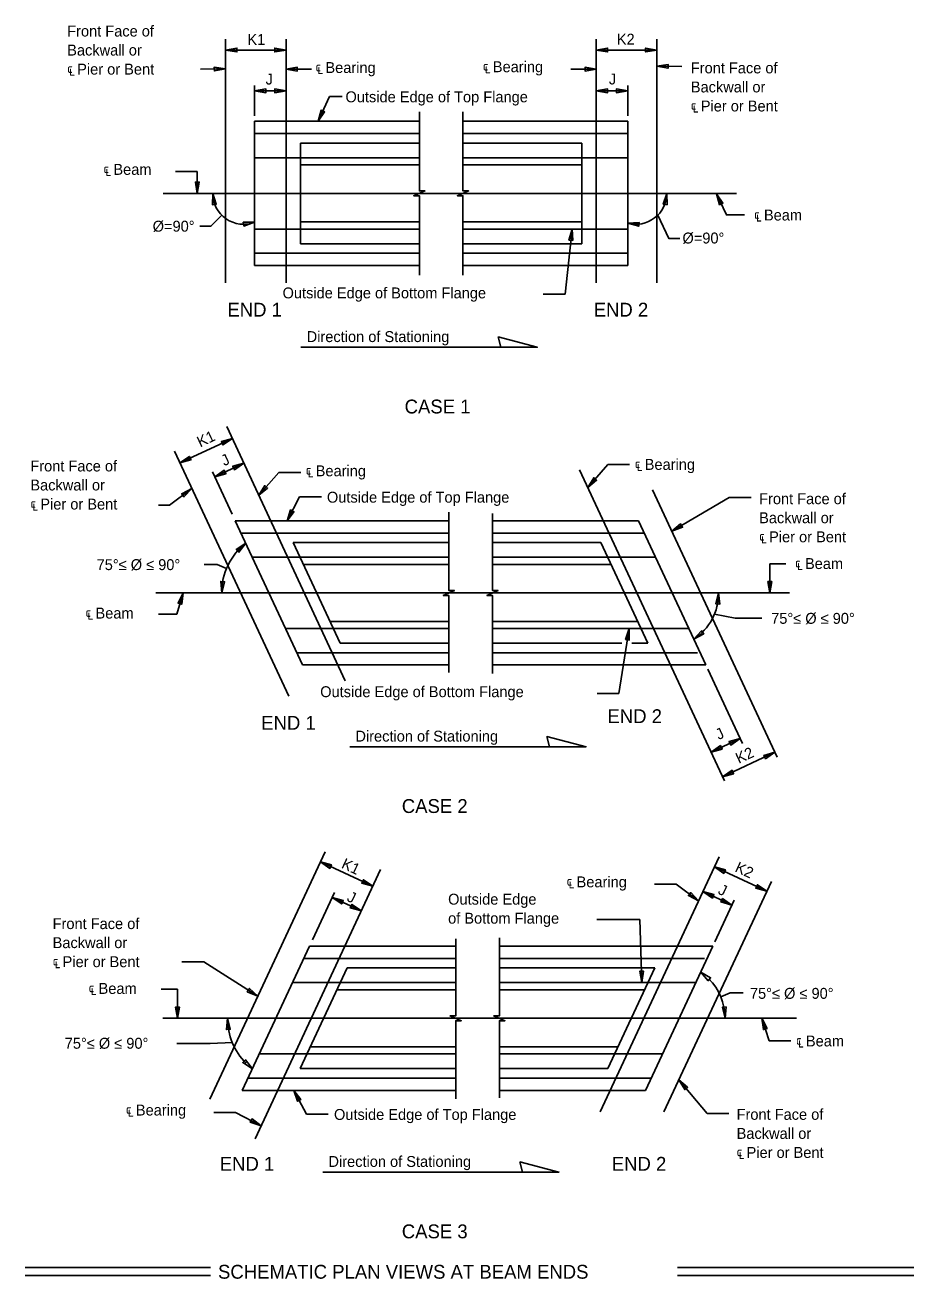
# Model space of a CAD drawing. Extents: x 0.2 to 12.5, y 1.6 to 19.
import ezdxf

# ---------------------------------------------------------------- set-up
doc = ezdxf.new("R2010")
doc.units = 0
for name, color, linetype in [('BeamConc', 7, 'Continuous'), ('BeamConc_h', 7, 'Continuous'), ('CL_Major', 7, 'Continuous'), ('Dimension', 7, 'Continuous'), ('TextStructures', 7, 'Continuous')]:
    doc.layers.add(name, color=color, linetype=linetype)

# ---------------------------------------------------------------- blocks, each defined once
blk = doc.blocks.new('Terminator-Arrow')
at = {"layer": 'Dimension'}
blk.add_lwpolyline([(0, 0), (-0.00041, 0.000069), (-0.00041, -0.000069)], close=True, dxfattribs=at)

msp = doc.modelspace()

# ---------------------------------------------------------------- linework, layer by layer
at = {"layer": 'BeamConc'}
for p, q in [((3.338, 17.632), (5.623, 17.632)), ((3.338, 15.632), (3.338, 17.632)), ((6.227, 17.632), (8.511, 17.632)), ((8.511, 15.632), (8.511, 17.632)), ((3.974, 15.934), (3.974, 17.33)), ((3.974, 17.33), (5.622, 17.33)), ((7.876, 17.33), (6.227, 17.33)), ((7.876, 15.934), (7.876, 17.33)), ((3.974, 17.027), (5.622, 17.027)), ((7.876, 17.027), (6.227, 17.027)), ((3.974, 16.237), (5.622, 16.237)), ((7.876, 16.237), (6.227, 16.237)), ((3.974, 15.934), (5.622, 15.934)), ((7.876, 15.934), (6.227, 15.934)), ((3.338, 15.632), (5.623, 15.632)), ((6.227, 15.632), (8.511, 15.632)), ((4.004, 10.092), (3.071, 12.092)), ((3.071, 12.092), (6.031, 12.092)), ((8.662, 12.092), (6.635, 12.092)), ((8.662, 12.092), (9.594, 10.092)), ((3.874, 11.79), (6.031, 11.79)), ((4.525, 10.394), (3.874, 11.79)), ((8.14, 11.79), (6.635, 11.79)), ((8.14, 11.79), (8.791, 10.394)), ((4.015, 11.487), (6.031, 11.487)), ((8.282, 11.487), (6.635, 11.487)), ((4.384, 10.697), (6.031, 10.697)), ((8.65, 10.697), (6.635, 10.697)), ((4.525, 10.394), (6.031, 10.394)), ((8.431, 10.394), (6.635, 10.394)), ((8.791, 10.394), (8.566, 10.394)), ((4.004, 10.092), (6.031, 10.092)), ((9.594, 10.092), (6.635, 10.092)), ((4.1, 6.194), (3.168, 4.194)), ((4.1, 6.194), (6.127, 6.194)), ((9.691, 6.194), (6.732, 6.194)), ((8.758, 4.194), (9.691, 6.194)), ((4.622, 5.892), (3.971, 4.495)), ((4.622, 5.892), (6.127, 5.892)), ((8.888, 5.892), (6.732, 5.892)), ((8.237, 4.495), (8.888, 5.892)), ((4.48, 5.589), (6.127, 5.589)), ((8.747, 5.589), (6.732, 5.589)), ((4.112, 4.798), (6.127, 4.798)), ((8.378, 4.798), (6.732, 4.798)), ((3.971, 4.495), (6.127, 4.495)), ((8.237, 4.495), (6.732, 4.495)), ((3.168, 4.194), (6.127, 4.194)), ((8.758, 4.194), (6.732, 4.194))]:
    msp.add_line(p, q, dxfattribs=at)
at = {"layer": 'BeamConc_h'}
for p, q in [((3.338, 17.462), (5.622, 17.462)), ((8.511, 17.462), (6.227, 17.462)), ((3.338, 17.127), (5.622, 17.127)), ((6.227, 17.127), (8.511, 17.127)), ((3.338, 16.137), (5.622, 16.137)), ((6.227, 16.137), (8.511, 16.137)), ((3.338, 15.802), (5.622, 15.802)), ((8.511, 15.802), (6.227, 15.802)), ((3.151, 11.922), (6.031, 11.922)), ((8.741, 11.922), (6.635, 11.922)), ((3.307, 11.587), (6.031, 11.587)), ((8.897, 11.587), (6.635, 11.587)), ((3.769, 10.597), (6.031, 10.597)), ((9.359, 10.597), (6.635, 10.597)), ((3.925, 10.262), (6.031, 10.262)), ((9.478, 10.262), (6.635, 10.262)), ((4.021, 6.024), (6.127, 6.024)), ((9.574, 6.024), (6.732, 6.024)), ((3.865, 5.689), (6.127, 5.689)), ((9.455, 5.689), (6.732, 5.689)), ((3.403, 4.698), (6.127, 4.698)), ((8.993, 4.698), (6.732, 4.698)), ((3.247, 4.363), (6.127, 4.363)), ((8.837, 4.363), (6.732, 4.363))]:
    msp.add_line(p, q, dxfattribs=at)
at = {"layer": 'CL_Major'}
for p, q in [((2.936, 15.392), (2.936, 18.77)), ((3.774, 15.392), (3.774, 18.77)), ((8.076, 15.392), (8.076, 18.77)), ((8.914, 15.392), (8.914, 18.77)), ((2.069, 16.632), (10.018, 16.632)), ((4.596, 9.874), (2.953, 13.398)), ((3.811, 9.661), (2.226, 13.059)), ((7.842, 12.799), (9.853, 8.487)), ((8.855, 12.523), (10.585, 8.812)), ((1.967, 11.092), (10.754, 11.092)), ((4.315, 7.499), (2.717, 4.072)), ((8.129, 3.895), (9.777, 7.431)), ((5.086, 7.257), (3.344, 3.52)), ((9.013, 3.895), (10.504, 7.092)), ((2.064, 5.194), (10.851, 5.194))]:
    msp.add_line(p, q, dxfattribs=at)
at = {"layer": 'Dimension'}
for p, q in [((2.936, 18.619), (3.774, 18.619)), ((2.936, 18.619), (3.774, 18.619)), ((8.914, 18.619), (8.076, 18.619)), ((8.914, 18.619), (8.076, 18.619)), ((2.936, 18.358), (2.587, 18.355)), ((2.936, 18.358), (2.587, 18.355)), ((3.774, 18.355), (3.827, 18.355)), ((3.774, 18.355), (3.827, 18.355)), ((3.827, 18.355), (4.129, 18.355)), ((3.827, 18.355), (4.129, 18.355)), ((8.023, 18.355), (7.721, 18.355)), ((8.023, 18.355), (7.721, 18.355)), ((8.914, 18.394), (9.263, 18.392)), ((8.914, 18.394), (9.263, 18.392)), ((3.338, 17.707), (3.338, 18.128)), ((3.338, 17.707), (3.338, 18.128)), ((8.511, 17.707), (8.511, 18.128)), ((8.511, 17.707), (8.511, 18.128)), ((3.338, 18.053), (3.774, 18.053)), ((3.338, 18.053), (3.774, 18.053)), ((4.219, 17.632), (4.377, 17.973)), ((4.219, 17.632), (4.377, 17.973)), ((4.377, 17.973), (4.551, 17.973)), ((4.377, 17.973), (4.551, 17.973)), ((8.511, 18.053), (8.076, 18.053)), ((8.511, 18.053), (8.076, 18.053)), ((2.544, 16.933), (2.241, 16.933)), ((2.544, 16.933), (2.241, 16.933)), ((2.544, 16.632), (2.544, 16.933)), ((2.544, 16.632), (2.544, 16.933)), ((7.74, 16.137), (7.643, 15.235)), ((7.74, 16.137), (7.643, 15.235)), ((7.643, 15.235), (7.34, 15.235)), ((7.643, 15.235), (7.34, 15.235)), ((7.257, 14.499), (3.981, 14.499)), ((2.303, 12.894), (3.03, 13.233)), ((2.303, 12.894), (3.03, 13.233)), ((2.787, 12.703), (3.189, 12.891)), ((2.787, 12.703), (3.189, 12.891)), ((7.957, 12.553), (8.234, 12.87)), ((7.957, 12.553), (8.234, 12.87)), ((8.234, 12.87), (8.537, 12.87)), ((8.234, 12.87), (8.537, 12.87)), ((3.028, 12.185), (2.755, 12.771)), ((3.028, 12.185), (2.755, 12.771)), ((3.396, 12.446), (3.674, 12.763)), ((3.396, 12.446), (3.674, 12.763)), ((3.674, 12.763), (3.977, 12.763)), ((3.674, 12.763), (3.977, 12.763)), ((2.469, 12.54), (2.16, 12.307)), ((2.469, 12.54), (2.16, 12.307)), ((3.788, 12.092), (3.962, 12.422)), ((3.788, 12.092), (3.962, 12.422)), ((3.962, 12.422), (4.264, 12.422)), ((3.962, 12.422), (4.264, 12.422)), ((9.124, 11.946), (9.919, 12.416)), ((9.124, 11.946), (9.919, 12.416)), ((9.919, 12.416), (10.222, 12.416)), ((9.919, 12.416), (10.222, 12.416)), ((2.16, 12.307), (2.008, 12.307)), ((2.16, 12.307), (2.008, 12.307)), ((10.48, 11.092), (10.482, 11.495)), ((10.48, 11.092), (10.482, 11.495)), ((10.482, 11.495), (10.705, 11.495)), ((10.482, 11.495), (10.705, 11.495)), ((2.348, 11.092), (2.259, 10.795)), ((2.348, 11.092), (2.259, 10.795)), ((2.259, 10.795), (2.007, 10.795)), ((2.259, 10.795), (2.007, 10.795)), ((8.531, 10.597), (8.39, 9.698)), ((8.531, 10.597), (8.39, 9.698)), ((9.621, 10.035), (9.936, 9.358)), ((9.621, 10.035), (9.936, 9.358)), ((8.39, 9.698), (8.087, 9.698)), ((8.39, 9.698), (8.087, 9.698)), ((9.936, 9.358), (10.102, 9.004)), ((9.936, 9.358), (10.102, 9.004)), ((10.07, 9.072), (9.667, 8.884)), ((10.07, 9.072), (9.667, 8.884)), ((7.933, 8.959), (4.658, 8.959)), ((10.553, 8.881), (9.827, 8.542)), ((10.553, 8.881), (9.827, 8.542)), ((4.977, 7.023), (4.251, 7.362)), ((4.977, 7.023), (4.251, 7.362)), ((10.44, 6.955), (9.713, 7.294)), ((10.44, 6.955), (9.713, 7.294)), ((9.185, 7.055), (8.883, 7.055)), ((9.185, 7.055), (8.883, 7.055)), ((9.494, 6.822), (9.185, 7.055)), ((9.494, 6.822), (9.185, 7.055)), ((4.14, 6.279), (4.447, 6.937)), ((4.14, 6.279), (4.447, 6.937)), ((4.818, 6.681), (4.415, 6.869)), ((4.818, 6.681), (4.415, 6.869)), ((9.956, 6.764), (9.554, 6.951)), ((9.956, 6.764), (9.554, 6.951)), ((9.718, 6.253), (9.988, 6.832)), ((9.718, 6.253), (9.988, 6.832)), ((8.68, 6.561), (8.082, 6.561)), ((8.68, 6.561), (8.082, 6.561)), ((8.709, 5.689), (8.68, 6.561)), ((8.709, 5.689), (8.68, 6.561)), ((2.633, 5.975), (2.331, 5.975)), ((2.633, 5.975), (2.331, 5.975)), ((3.383, 5.501), (2.633, 5.975)), ((3.383, 5.501), (2.633, 5.975)), ((2.268, 5.595), (2.045, 5.595)), ((2.268, 5.595), (2.045, 5.595)), ((2.27, 5.194), (2.268, 5.595)), ((2.27, 5.194), (2.268, 5.595)), ((10.37, 5.194), (10.471, 4.88)), ((10.37, 5.194), (10.471, 4.88)), ((10.471, 4.88), (10.773, 4.88)), ((10.471, 4.88), (10.773, 4.88)), ((3.884, 4.194), (4.058, 3.864)), ((3.884, 4.194), (4.058, 3.864)), ((9.221, 4.34), (9.613, 3.873)), ((9.221, 4.34), (9.613, 3.873)), ((3.075, 3.886), (2.772, 3.886)), ((3.075, 3.886), (2.772, 3.886)), ((3.429, 3.702), (3.075, 3.886)), ((3.429, 3.702), (3.075, 3.886)), ((4.058, 3.864), (4.36, 3.864)), ((4.058, 3.864), (4.36, 3.864)), ((9.613, 3.873), (9.915, 3.873)), ((9.613, 3.873), (9.915, 3.873)), ((7.558, 3.06), (4.283, 3.06)), ((2.726, 1.735), (0.156, 1.735)), ((2.726, 1.627), (0.156, 1.627)), ((12.479, 1.735), (9.202, 1.735)), ((12.479, 1.627), (9.202, 1.627))]:
    msp.add_line(p, q, dxfattribs=at)
for points in [[(5.623, 17.761), (5.623, 16.666), (5.7, 16.666), (5.545, 16.598), (5.623, 16.598), (5.623, 15.496)], [(5.623, 17.761), (5.623, 16.666), (5.7, 16.666), (5.545, 16.598), (5.623, 16.598), (5.623, 15.496)], [(6.227, 17.761), (6.227, 16.666), (6.305, 16.666), (6.15, 16.598), (6.227, 16.598), (6.227, 15.496)], [(6.227, 17.761), (6.227, 16.666), (6.305, 16.666), (6.15, 16.598), (6.227, 16.598), (6.227, 15.496)], [(9.74, 16.627), (9.88, 16.333), (10.131, 16.333)], [(9.74, 16.627), (9.88, 16.333), (10.131, 16.333)], [(2.883, 16.329), (2.732, 16.177), (2.578, 16.177)], [(8.928, 16.329), (9.079, 16.008), (9.233, 16.008)], [(8.928, 16.329), (9.079, 16.008), (9.233, 16.008)], [(6.031, 12.209), (6.031, 11.126), (6.108, 11.126), (5.953, 11.058), (6.031, 11.058), (6.031, 9.989)], [(6.031, 12.209), (6.031, 11.126), (6.108, 11.126), (5.953, 11.058), (6.031, 11.058), (6.031, 9.989)], [(6.635, 9.975), (6.635, 11.058), (6.558, 11.058), (6.713, 11.126), (6.635, 11.126), (6.635, 12.195)], [(6.635, 9.975), (6.635, 11.058), (6.558, 11.058), (6.713, 11.126), (6.635, 11.126), (6.635, 12.195)], [(2.95, 11.43), (2.82, 11.484), (2.641, 11.484)], [(2.95, 11.43), (2.82, 11.484), (2.641, 11.484)], [(9.713, 10.796), (10, 10.742), (10.067, 10.742)], [(9.713, 10.796), (10, 10.742), (10.372, 10.742)], [(6.127, 4.076), (6.127, 5.16), (6.204, 5.16), (6.049, 5.227), (6.127, 5.227), (6.127, 6.297)], [(6.127, 4.076), (6.127, 5.16), (6.204, 5.16), (6.049, 5.227), (6.127, 5.227), (6.127, 6.297)], [(6.732, 6.311), (6.732, 5.227), (6.654, 5.227), (6.809, 5.16), (6.732, 5.16), (6.732, 4.091)], [(6.732, 6.311), (6.732, 5.227), (6.654, 5.227), (6.809, 5.16), (6.732, 5.16), (6.732, 4.091)], [(9.803, 5.49), (9.933, 5.544), (10.112, 5.544)], [(3.03, 4.856), (2.721, 4.842), (2.262, 4.842)]]:
    msp.add_lwpolyline(points, dxfattribs=at)
for points in [[(2.758, 16.632), (2.754, 16.473), (2.806, 16.481)], [(9.053, 16.632), (9.057, 16.473), (9.004, 16.481)], [(9.74, 16.627), (9.832, 16.497), (9.784, 16.474)], [(9.74, 16.627), (9.832, 16.497), (9.784, 16.474)], [(3.338, 16.231), (3.18, 16.232), (3.189, 16.179)], [(8.511, 16.218), (8.669, 16.229), (8.664, 16.176)], [(3.216, 11.783), (3.084, 11.694), (3.121, 11.656)], [(2.883, 11.092), (2.921, 11.246), (2.868, 11.25)], [(9.772, 11.092), (9.734, 10.938), (9.787, 10.934)], [(9.428, 10.448), (9.566, 10.526), (9.533, 10.567)], [(9.956, 6.763), (9.804, 6.806), (9.826, 6.853)], [(9.956, 6.763), (9.804, 6.806), (9.826, 6.853)], [(9.914, 6.783), (9.812, 6.813), (9.826, 6.842)], [(9.914, 6.783), (9.812, 6.813), (9.826, 6.842)], [(9.876, 6.801), (9.823, 6.816), (9.831, 6.832)], [(9.876, 6.801), (9.823, 6.816), (9.831, 6.832)], [(9.523, 5.834), (9.66, 5.755), (9.627, 5.714)], [(9.862, 5.194), (9.824, 5.347), (9.876, 5.351)], [(2.962, 5.194), (3, 5.04), (2.948, 5.036)], [(3.307, 4.493), (3.174, 4.579), (3.21, 4.618)]]:
    msp.add_lwpolyline(points, close=True, dxfattribs=at)
for centre, radius, start, end in [((3.186, 16.632), 0.429, 180, 290.7788), ((8.624, 16.632), 0.429, 254.6951, 0), ((3.766, 11.092), 0.884, 128.5493, 180), ((8.998, 11.092), 0.774, 303.7741, 0), ((9.087, 5.194), 0.774, 0, 44.9892), ((3.846, 5.194), 0.884, 180, 224.9892)]:
    msp.add_arc(centre, radius, start, end, dxfattribs=at)
at = {"layer": 'TextStructures'}
for points in [[(6.714, 14.642), (6.75, 14.499), (7.257, 14.499)], [(7.39, 9.102), (7.426, 8.959), (7.933, 8.959)], [(7.016, 3.204), (7.051, 3.06), (7.558, 3.06)]]:
    msp.add_lwpolyline(points, close=True, dxfattribs=at)

# ---------------------------------------------------------------- block references
at = {"layer": 'Dimension'}
for p, xscale, yscale, rotation in [((2.936, 18.619), 381, 384.0238095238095, 180), ((2.936, 18.619), 381, 384.0238095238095, 180), ((8.076, 18.619), 381, 384.0238095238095, 180), ((8.076, 18.619), 381, 384.0238095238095, 180), ((2.936, 18.358), 380.99999999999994, 384.02380952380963, 0.37716899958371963), ((2.936, 18.358), 380.99999999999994, 384.02380952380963, 0.37716899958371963), ((3.774, 18.355), 381.00000000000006, 384.0238095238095, -179.96491509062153), ((3.774, 18.355), 381.00000000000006, 384.0238095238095, -179.96491509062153), ((8.076, 18.355), 381, 384.0238095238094, -0.03510757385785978), ((8.076, 18.355), 381, 384.0238095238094, -0.03510757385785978), ((8.914, 18.394), 381, 384.0238095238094, 179.62286774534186), ((8.914, 18.394), 381, 384.0238095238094, 179.62286774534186), ((3.338, 18.053), 381, 384.0238095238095, 180), ((3.338, 18.053), 381, 384.0238095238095, 180), ((8.076, 18.053), 381, 384.0238095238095, 180), ((8.076, 18.053), 381, 384.0238095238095, 180), ((4.219, 17.632), 381, 384.0238095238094, -114.94557593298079), ((4.219, 17.632), 381, 384.0238095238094, -114.94557593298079), ((2.544, 16.632), 381, 384.0238095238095, -90), ((2.544, 16.632), 381, 384.0238095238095, -90), ((7.74, 16.137), 381, 384.0238095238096, 83.8251389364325), ((7.74, 16.137), 381, 384.0238095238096, 83.8251389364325), ((3.03, 13.233), 381, 384.0238095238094, 24.9944758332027), ((3.03, 13.233), 381, 384.0238095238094, 24.9944758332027), ((2.303, 12.894), 381, 384.0238095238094, -155.0055241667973), ((2.303, 12.894), 381, 384.0238095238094, -155.0055241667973), ((3.189, 12.89), 380.99999999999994, 384.0238095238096, 24.994475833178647), ((3.189, 12.89), 380.99999999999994, 384.0238095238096, 24.994475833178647), ((2.787, 12.703), 380.99999999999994, 384.0238095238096, -155.00552416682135), ((2.787, 12.703), 380.99999999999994, 384.0238095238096, -155.00552416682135), ((2.468, 12.539), 381, 384.0238095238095, 36.99205670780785), ((2.468, 12.539), 381, 384.0238095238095, 36.99205670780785), ((3.396, 12.446), 381, 384.0238095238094, -131.21867682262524), ((3.396, 12.446), 381, 384.0238095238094, -131.21867682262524), ((7.957, 12.553), 381, 384.0238095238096, -131.21941588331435), ((7.957, 12.553), 381, 384.0238095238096, -131.21941588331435), ((3.788, 12.092), 381, 384.0238095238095, -117.72534965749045), ((3.788, 12.092), 381, 384.0238095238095, -117.72534965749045), ((9.124, 11.946), 381.00000000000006, 384.0238095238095, -149.40161216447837), ((9.124, 11.946), 381.00000000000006, 384.0238095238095, -149.40161216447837), ((10.48, 11.092), 380.99999999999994, -384.02380952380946, -90.31997310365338), ((10.48, 11.092), 380.99999999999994, -384.02380952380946, -90.31997310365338), ((2.348, 11.092), 380.99999999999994, 384.0238095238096, 73.21326448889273), ((2.348, 11.092), 380.99999999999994, 384.0238095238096, 73.21326448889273), ((8.531, 10.597), 381, 384.0238095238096, 81.04426286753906), ((8.531, 10.597), 381, 384.0238095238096, 81.04426286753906), ((10.07, 9.072), 381, 384.0238095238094, 24.9944758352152), ((10.07, 9.072), 381, 384.0238095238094, 24.9944758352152), ((9.667, 8.884), 381, 384.0238095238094, -155.00552416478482), ((9.667, 8.884), 381, 384.0238095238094, -155.00552416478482), ((10.553, 8.881), 381, 384.0238095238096, 24.994475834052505), ((10.553, 8.881), 381, 384.0238095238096, 24.994475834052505), ((9.827, 8.542), 381, 384.0238095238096, -155.00552416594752), ((9.827, 8.542), 381, 384.0238095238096, -155.00552416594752), ((4.251, 7.362), 381, 384.0238095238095, 155.0055241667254), ((4.251, 7.362), 381, 384.0238095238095, 155.0055241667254), ((9.713, 7.293), 381, 384.0238095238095, 155.00552416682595), ((9.713, 7.293), 381, 384.0238095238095, 155.00552416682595), ((4.977, 7.023), 381, 384.0238095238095, -24.994475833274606), ((4.977, 7.023), 381, 384.0238095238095, -24.994475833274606), ((9.554, 6.951), 381.00000000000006, 384.0238095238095, 155.00552416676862), ((9.554, 6.951), 381.00000000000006, 384.0238095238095, 155.00552416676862), ((10.44, 6.955), 381, 384.0238095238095, -24.994475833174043), ((10.44, 6.955), 381, 384.0238095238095, -24.994475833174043), ((4.415, 6.868), 381, 384.0238095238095, 155.0055241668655), ((4.415, 6.868), 381, 384.0238095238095, 155.0055241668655), ((9.494, 6.822), 381, 384.0238095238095, -36.99636030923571), ((9.494, 6.822), 381, 384.0238095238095, -36.99636030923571), ((4.818, 6.681), 381, 384.0238095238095, -24.99447583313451), ((4.818, 6.681), 381, 384.0238095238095, -24.99447583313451), ((8.709, 5.689), 380.99999999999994, 384.0238095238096, -88.11192467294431), ((8.709, 5.689), 380.99999999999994, 384.0238095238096, -88.11192467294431), ((3.383, 5.501), 381.00000000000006, 384.0238095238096, -32.331988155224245), ((3.383, 5.501), 381.00000000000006, 384.0238095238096, -32.331988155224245), ((2.27, 5.193), 380.99999999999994, 384.02380952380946, -89.68002689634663), ((2.27, 5.193), 380.99999999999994, 384.02380952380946, -89.68002689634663), ((10.37, 5.194), 381, 384.0238095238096, 107.77364180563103), ((10.37, 5.194), 381, 384.0238095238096, 107.77364180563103), ((9.221, 4.34), 381, 384.0238095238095, 130.02223544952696), ((9.221, 4.34), 381, 384.0238095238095, 130.02223544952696), ((3.884, 4.194), 381, 384.0238095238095, 117.72534965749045), ((3.884, 4.194), 381, 384.0238095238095, 117.72534965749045), ((3.429, 3.702), 381, 384.0238095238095, -27.50080843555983), ((3.429, 3.702), 381, 384.0238095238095, -27.50080843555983)]:
    msp.add_blockref('Terminator-Arrow', p, dxfattribs=dict(at, xscale=xscale, yscale=yscale, rotation=rotation))
at = {"layer": 'Dimension', "xscale": 381, "yscale": 384.0238095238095}
for p in [(3.774, 18.619), (3.774, 18.619), (8.914, 18.619), (8.914, 18.619), (3.774, 18.053), (3.774, 18.053), (8.511, 18.053), (8.511, 18.053)]:
    msp.add_blockref('Terminator-Arrow', p, dxfattribs=at)

# ---------------------------------------------------------------- texts
at = {"layer": 'Dimension'}
for s, p in [('Front Face of', (0.74, 18.807)), ('Backwall or', (0.74, 18.543)), ('℄ Pier or Bent', (0.74, 18.279)), ('Front Face of', (9.386, 18.296)), ('Backwall or', (9.386, 18.032)), ('℄ Pier or Bent', (9.386, 17.768)), ('Front Face of', (0.229, 12.776)), ('Backwall or', (0.229, 12.512)), ('℄ Pier or Bent', (0.229, 12.248)), ('Front Face of', (10.333, 12.322)), ('Backwall or', (10.333, 12.058)), ('℄ Pier or Bent', (10.333, 11.794)), ('Front Face of', (0.538, 6.43)), ('Backwall or', (0.538, 6.166)), ('℄ Pier or Bent', (0.538, 5.902)), ('Front Face of', (10.021, 3.785)), ('Backwall or', (10.021, 3.521)), ('℄ Pier or Bent', (10.021, 3.257))]:
    msp.add_text(s, height=0.1512, dxfattribs=at).set_placement(p)
at = {"layer": 'TextStructures'}
for s, height, p in [('K1', 0.1512, (3.238, 18.69)), ('K2', 0.1512, (8.36, 18.694)), ('℄ Bearing', 0.1512, (4.182, 18.301)), ('℄ Bearing', 0.1512, (6.503, 18.312)), ('J', 0.151, (3.491, 18.141)), ('J', 0.151, (8.25, 18.142)), ('Outside Edge of Top Flange', 0.1512, (4.598, 17.895)), ('℄ Beam', 0.1512, (1.242, 16.889)), ('℄ Beam', 0.1512, (10.262, 16.256)), ('Ø=90°', 0.1512, (1.925, 16.101)), ('Ø=90°', 0.1512, (9.27, 15.937)), ('Outside Edge of Bottom Flange', 0.1512, (3.726, 15.176)), ('END 1', 0.192, (2.961, 14.923)), ('END 2', 0.192, (8.039, 14.923)), ('Direction of Stationing', 0.1512, (4.06, 14.57)), ('CASE 1', 0.192, (5.418, 13.58)), ('℄ Bearing', 0.1512, (4.047, 12.709)), ('℄ Bearing', 0.1512, (4.047, 12.709)), ('℄ Bearing', 0.1512, (8.609, 12.798)), ('Outside Edge of Top Flange', 0.1512, (4.341, 12.343)), ('75°≤ Ø ≤ 90°', 0.1512, (1.148, 11.408)), ('℄ Beam', 0.1512, (10.831, 11.423)), ('℄ Beam', 0.1512, (0.994, 10.736)), ('75°≤ Ø ≤ 90°', 0.1512, (10.5, 10.663)), ('Outside Edge of Bottom Flange', 0.1512, (4.248, 9.646)), ('END 2', 0.192, (8.23, 9.286)), ('END 1', 0.192, (3.43, 9.194)), ('Direction of Stationing', 0.1512, (4.736, 9.03)), ('CASE 2', 0.192, (5.379, 8.04)), ('℄ Bearing', 0.1512, (7.664, 7.009)), ('Outside Edge', 0.1512, (6.021, 6.769)), ('of Bottom Flange', 0.1512, (6.021, 6.505)), ('℄ Beam', 0.1512, (1.037, 5.531)), ('75°≤ Ø ≤ 90°', 0.1512, (10.206, 5.463)), ('75°≤ Ø ≤ 90°', 0.1512, (0.706, 4.771)), ('℄ Beam', 0.1512, (10.844, 4.803)), ('℄ Bearing', 0.1512, (1.554, 3.845)), ('Outside Edge of Top Flange', 0.1512, (4.439, 3.784)), ('END 1', 0.192, (2.855, 3.079)), ('Direction of Stationing', 0.1512, (4.362, 3.132)), ('END 2', 0.192, (8.29, 3.079)), ('CASE 3', 0.192, (5.379, 2.142)), ('SCHEMATIC PLAN VIEWS AT BEAM ENDS', 0.192, (2.831, 1.582))]:
    msp.add_text(s, height=height, dxfattribs=at).set_placement(p)
for s, height, rotation, p in [('K1', 0.1512, 24.9945, (2.583, 13.108)), ('J', 0.151, 24.9945, (2.917, 12.847)), ('J', 0.151, 24.9945, (9.772, 9.05)), ('K2', 0.1512, 24.9945, (10.051, 8.72)), ('K1', 0.1512, 335.0055, (4.53, 7.283)), ('K2', 0.1512, 335.0055, (9.986, 7.233)), ('J', 0.151, 335.0055, (9.752, 6.924)), ('J', 0.151, 335.0055, (4.607, 6.825))]:
    msp.add_text(s, height=height, rotation=rotation, dxfattribs=at).set_placement(p)

doc.saveas('drawing.dxf')
